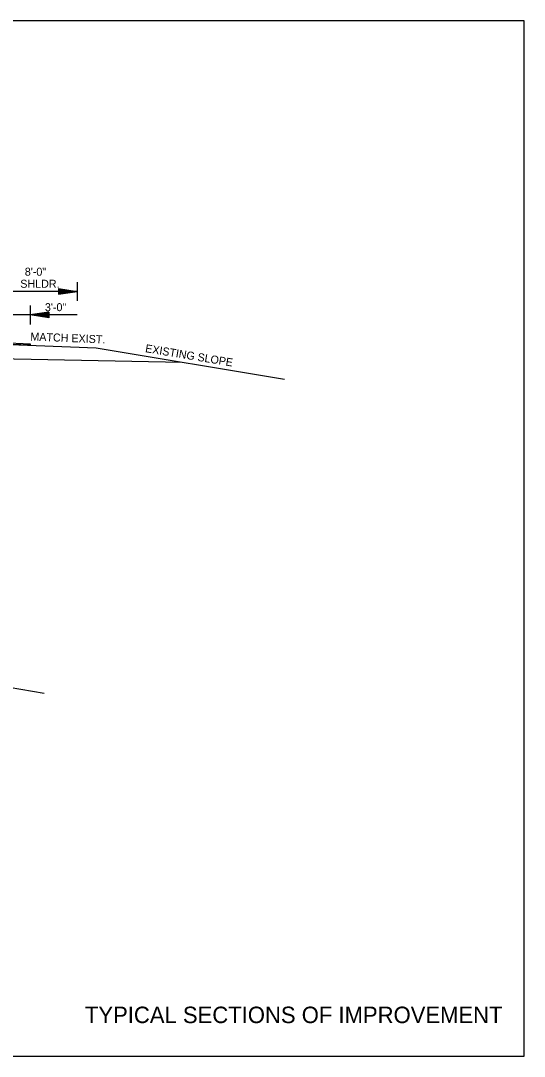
# Model space of a CAD drawing. Extents: x 2261938 to 2263136, y -3124572 to -3124216.
# Drawn here: x 2262793.4 to 2262846.9, y -3124556.1 to -3124446.1 of the extents above; entities that cross this region are included whole.
import ezdxf

# ---------------------------------------------------------------- set-up
doc = ezdxf.new("R2010")
doc.units = 0
for name, color, linetype in [('DSN_DRFT_Common-Annotations', 7, 'Continuous'), ('DSN_DRFT_Common-Line', 7, 'Continuous'), ('DSN_DRFT_Dimension', 7, 'Continuous'), ('SHET_Border-Text', 7, 'Continuous')]:
    doc.layers.add(name, color=color, linetype=linetype)

msp = doc.modelspace()

# ---------------------------------------------------------------- linework, layer by layer
at = {"layer": 'DSN_DRFT_Common-Line'}
for p, q in [((2262799.44, -3124473.86), (2262799.44, -3124475.86)), ((2262794.44, -3124476.36), (2262794.44, -3124478.36)), ((2262791.44, -3124480.45), (2262801.44, -3124480.85)), ((2262761.94, -3124481.4), (2262810.59, -3124482.38)), ((2262801.44, -3124480.85), (2262821.44, -3124484.19)), ((2262775.94, -3124514.19), (2262795.94, -3124517.53))]:
    msp.add_line(p, q, dxfattribs=at)
for points in [[(2262676.9, -3124446.1), (2262676.9, -3124556.1), (2262846.9, -3124556.1), (2262846.9, -3124446.1)], [(2262791.44, -3124480.45), (2262761.94, -3124479.86), (2262732.44, -3124480.45), (2262729.44, -3124480.57), (2262729.44, -3124480.41), (2262732.44, -3124480.29), (2262761.94, -3124479.7), (2262791.44, -3124480.29), (2262794.44, -3124480.41), (2262794.44, -3124480.57)]]:
    msp.add_lwpolyline(points, close=True, dxfattribs=at)
at = {"layer": 'DSN_DRFT_Dimension'}
for p, q in [((2262799.44, -3124474.86), (2262791.44, -3124474.86)), ((2262797.44, -3124474.56), (2262799.44, -3124474.86)), ((2262797.44, -3124474.56), (2262797.44, -3124475.16)), ((2262797.44, -3124474.61), (2262799.1, -3124474.86)), ((2262797.44, -3124474.66), (2262798.76, -3124474.86)), ((2262797.44, -3124474.71), (2262798.43, -3124474.86)), ((2262797.44, -3124474.77), (2262798.09, -3124474.86)), ((2262797.44, -3124474.82), (2262797.75, -3124474.86)), ((2262797.44, -3124475.16), (2262799.44, -3124474.86)), ((2262797.44, -3124474.96), (2262798.09, -3124474.86)), ((2262797.44, -3124475.06), (2262798.76, -3124474.86)), ((2262797.44, -3124475.11), (2262799.1, -3124474.86)), ((2262797.44, -3124475.01), (2262798.43, -3124474.86)), ((2262797.44, -3124474.91), (2262797.75, -3124474.86)), ((2262799.44, -3124477.36), (2262787.44, -3124477.36)), ((2262796.44, -3124477.06), (2262794.44, -3124477.36)), ((2262796.44, -3124477.66), (2262794.44, -3124477.36)), ((2262796.44, -3124477.11), (2262794.77, -3124477.36)), ((2262796.44, -3124477.61), (2262794.77, -3124477.36)), ((2262796.44, -3124477.16), (2262795.12, -3124477.36)), ((2262796.44, -3124477.56), (2262795.12, -3124477.36)), ((2262796.44, -3124477.21), (2262795.45, -3124477.36)), ((2262796.44, -3124477.51), (2262795.45, -3124477.36)), ((2262796.44, -3124477.27), (2262795.79, -3124477.36)), ((2262796.44, -3124477.46), (2262795.79, -3124477.36)), ((2262796.44, -3124477.32), (2262796.12, -3124477.36)), ((2262796.44, -3124477.41), (2262796.12, -3124477.36)), ((2262796.44, -3124477.06), (2262796.44, -3124477.66))]:
    msp.add_line(p, q, dxfattribs=at)

# ---------------------------------------------------------------- texts
at = {"layer": 'DSN_DRFT_Common-Annotations'}
for s, p in [('8\'-0"', (2262793.88, -3124473.19)), ('SHLDR.', (2262793.4, -3124474.47)), (' 3\'-0"', (2262795.7, -3124476.96))]:
    msp.add_text(s, height=0.85, dxfattribs=at).set_placement(p)
for s, rotation, p in [('MATCH EXIST.', 357.7094, (2262794.46, -3124480.07)), ('EXISTING SLOPE', 350.538, (2262806.62, -3124481.3))]:
    msp.add_text(s, height=0.85, rotation=rotation, dxfattribs=at).set_placement(p)
at = {"layer": 'SHET_Border-Text'}
msp.add_text('TYPICAL SECTIONS OF IMPROVEMENT', height=1.75, dxfattribs=at).set_placement((2262800.26, -3124552.58))

doc.saveas('drawing.dxf')
